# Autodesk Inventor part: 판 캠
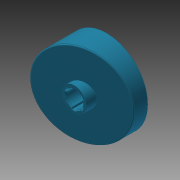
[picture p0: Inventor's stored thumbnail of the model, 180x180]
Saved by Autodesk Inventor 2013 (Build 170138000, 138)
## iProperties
Created: 2015-11
Part Number: 판 캠
Document SubType Name: 모델링
Designer: mdu
Material: 강철, 연강
Density: 7.86 g/cm^3
Mass: 682.51 g
Surface Area: 331.395 cm^2
Volume: 86.8333 cm^3
변환 표준: STEP AP214IS
파일 이름: C:\Users\SeoGD\Desktop\?쒗뿕\??stp
전처리기: Build: 253, Release: 2010 SP1 - Date: Wed 07/29/2009
전송 단위: 밀리미터
불확실성: 0.01
Author: mdu
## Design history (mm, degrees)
node "작업 평면4"
sketch "스케치1"
  geometry: C1 r 44.5 at (0, 0); 1 further point
  constraints: 1 centre point, 1 coincident
  dimensions: "d25" = 89 diameter of C1
extrude "돌출1" new body sketch "스케치1" distance "d1" = 40; taper "d2" = 0 deg
sketch "스케치2"
  geometry: L1 (-44.5, 15)-(44.5, 38.847); L2 (-44.5, 0)-(-44.5, 40) reference; L3 (-44.5, 40)-(44.5, 40) reference; L4 (44.5, 0)-(44.5, 40) reference; 1 further point
  constraints: 2 end point, 2 point on line
  dimensions: "d26" = 15 distance of L2.start L1.start; "d27" = 75 deg angle of L1 L2
extrude "돌출2" cut sketch "스케치2" stored distance "d5" = 40; taper "d6" = 0 deg
node "작업 평면1"
sketch "스케치3"
  geometry: C1 r 13 at (0, 0); 1 further point
  constraints: 1 centre point, 1 coincident
  dimensions: "d9" = 26 diameter of C1
extrude "돌출3" join sketch "스케치3" distance "d10" = 38; taper "d11" = 0 deg
hole "구멍1" diameter "d14" = 18; stored, may be unused: countersink angle "d18" = 90 deg, drill point angle "d20" = 118 deg; dims "d12" = 10, "d13" = 10, "d15" = 6, "d16" = 4, "d17" = 2, "d19" = 8
feature "쉘2" dims "d29" = 5
sketch "스케치6"
  geometry: C1 r 17.5 at (0, 0); C2 r 14 at (0, 0) reference; 1 further point
  constraints: 1 centre point, 1 coincident
  dimensions: "d28" = 35 diameter of C1
extrude "돌출4" join sketch "스케치6" stored distance "d30" = 38; taper "d31" = 0 deg
fillet "모깎기1" dims "d32" = 3
chamfer "모따기1" distance "d21" = 1; stored, may be unused: second distance "d22" = 2, angle "d23" = 45 deg
sketch "스케치7"
  geometry: L1 (-12.374, 12.374)-(-27.931, 27.931); A1 r 39.5 centre (0, 0) between (-27.931, 27.931) and (0, 39.5) reference; 2 further points
  constraints: 2 end point, 2 point on circle, 1 point on line, 1 vertical alignment, 2 other
  dimensions: "d33" = 45 deg dimension on point (0, 0) L1.start A1.end
feature "리브1" sketch "스케치7" dims "d34" = 5, "d35" = 1, "d36" = 0
fillet "모깎기2" dims "d37" = 3
sketch "스케치8"
  geometry: L1 (2.5, 10.712)-(2.5, 8.646); L2 (-2.5, 10.712)-(-2.5, 8.646); A1 r 11 centre (0, 0) between (2.5, 10.712) and (-2.5, 10.712); A2 r 9 centre (0, 0) between (2.5, 8.646) and (-2.5, 8.646) reference; 1 further point
  constraints: 4 end point, 4 point on circle, 2 parallel, 1 centre point, 1 coincident, 1 vertical
  dimensions: "d41" = 22 diameter of A1; "d42" = 5 distance between parallel lines of L1 L2
extrude "돌출5" cut sketch "스케치8" stored distance "d43" = 38; taper "d44" = 0 deg
fillet "모깎기3" dims "d48" = 1
node "작업 평면5"
sketch "스케치9"
  geometry: C1 r 1.5 at (0, 30); 1 further point
  constraints: 1 centre point, 1 vertical alignment
  dimensions: "d50" = 3 diameter of C1; "d52" = 30 distance of point (0, 0) C1.centre
extrude "돌출6" cut sketch "스케치9" distance "d53" = 1; taper "d54" = 0 deg
node "솔리드1"
node "솔리드 본체"
node "곡면 본체"
pattern_circular "원형 패턴1" dims angle "d39" = 360 deg
pattern_circular "원형 패턴2" dims angle "d46" = 360 deg
node "솔리드2"
other parameters: "d49" = -44.5
